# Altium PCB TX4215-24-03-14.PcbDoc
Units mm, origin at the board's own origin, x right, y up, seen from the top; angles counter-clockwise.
Board outline 80.29 x 57.18 mm, 2 copper layers (TopLayer, BottomLayer); 39 components, 49 nets, 94 pads, 680 vias.
Unrouted connection lines stored in the file: 1.
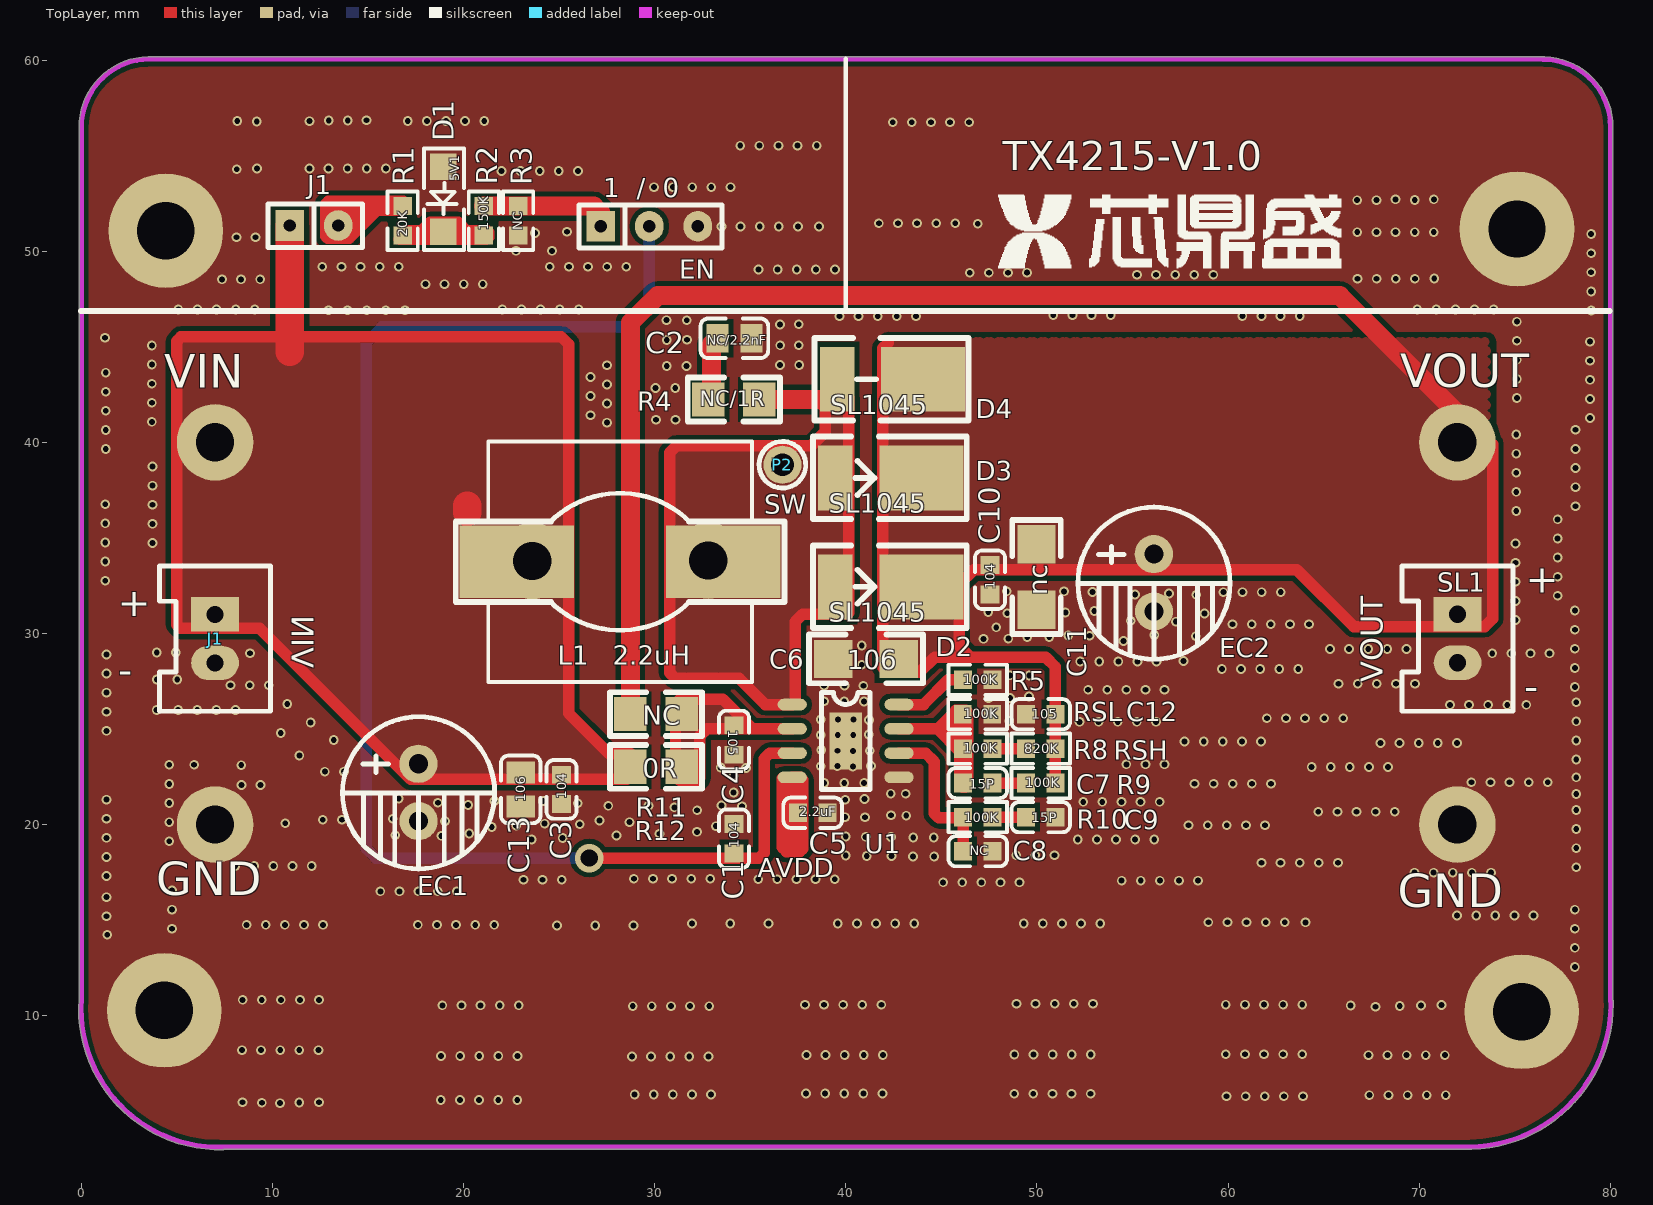
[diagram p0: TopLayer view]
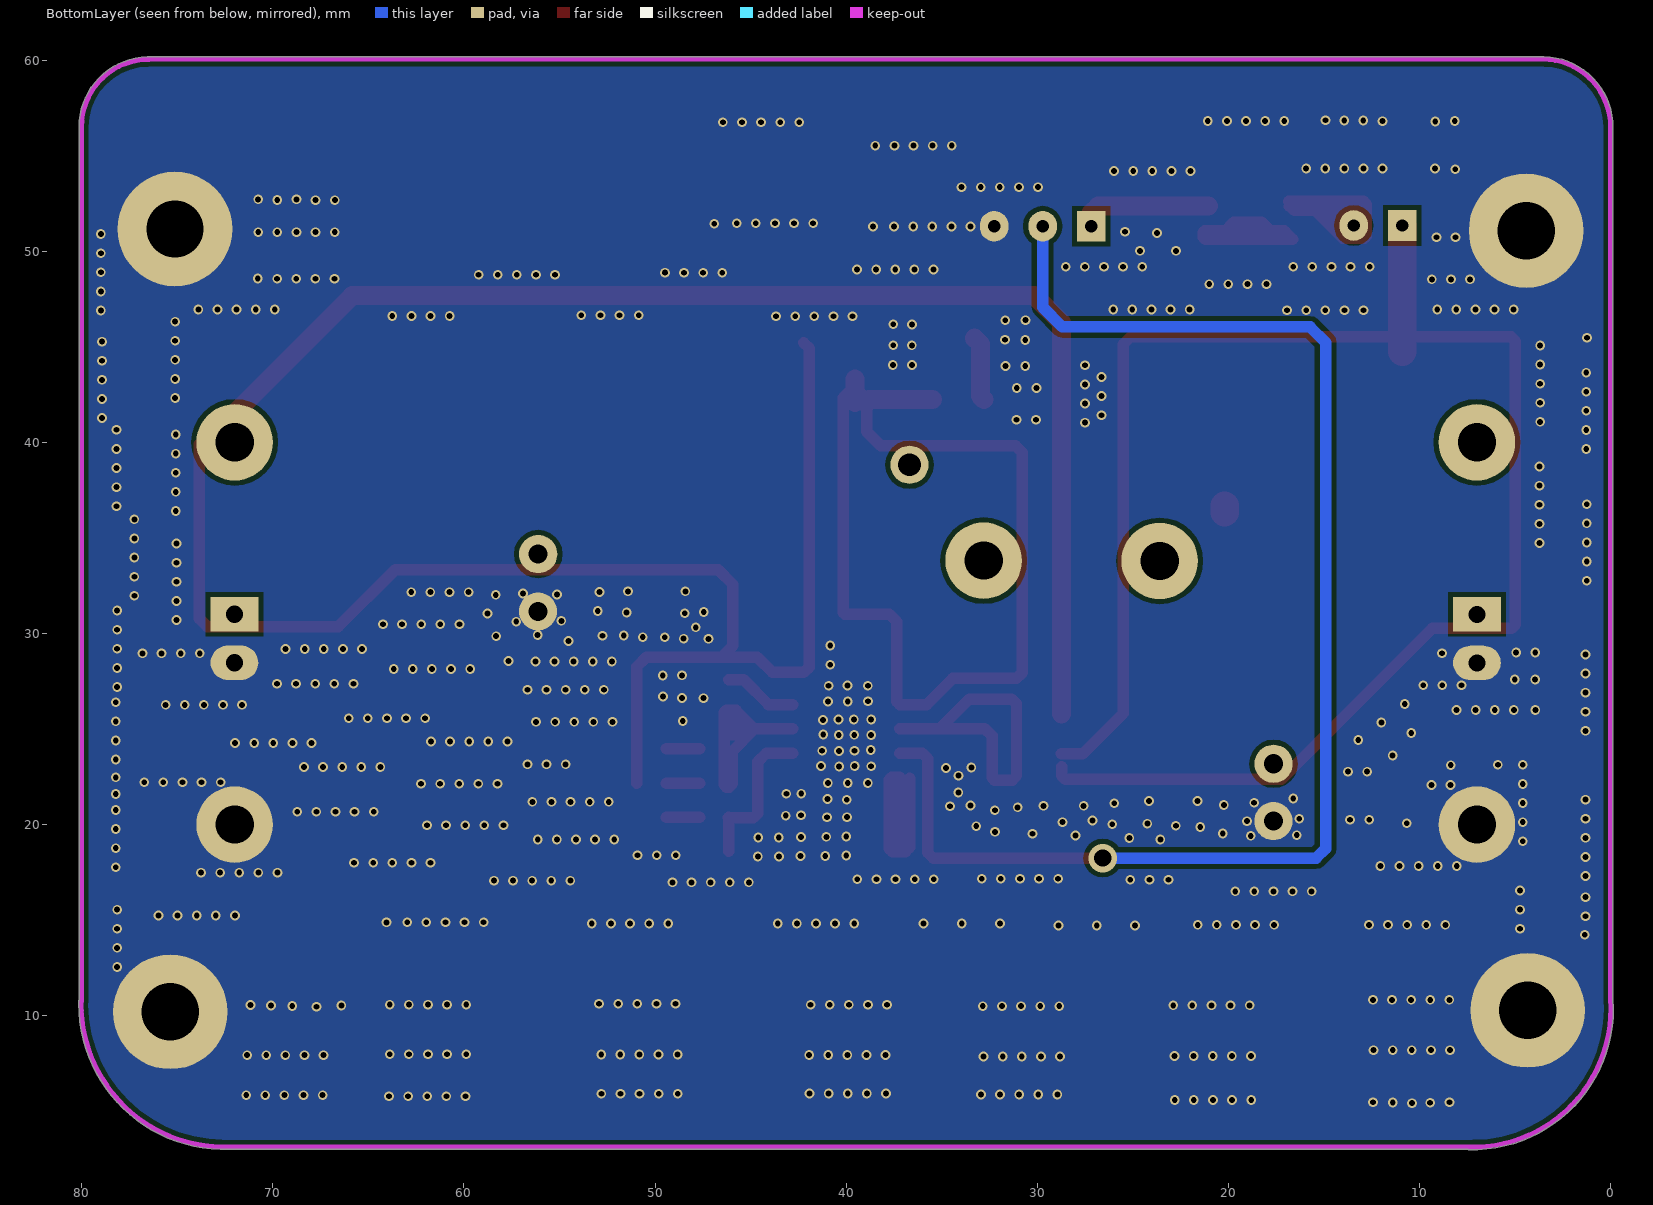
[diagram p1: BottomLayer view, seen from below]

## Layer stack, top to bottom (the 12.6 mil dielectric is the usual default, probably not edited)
TopLayer: signal copper 0.0356
Dielectric: dielectric 0.32, FR-4, Dk 4.8
BottomLayer: signal copper 0.0356

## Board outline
-0.117,10.893 -0.117,56.479 cw(c0.01,56.486) -0.117,56.486 cw(c3.569,56.491) 3.498,60.177 cw(c3.506,60.05) 3.506,60.177 3.514,60.177 cw(c3.569,56.491) 3.563,60.177 cw(c3.564,60.05) 3.574,60.177 76.515,60.177 cw(c76.515,60.05) 76.566,60.166 cw(c76.481,56.511) 80.137,56.511 cw(c76.481,56.511) 80.137,56.509 cw(c80.01,56.5) 80.138,56.5 80.138,10.809 cw(c80.03,10.741) 80.157,10.743 cw(c72.537,10.626) 80.158,10.626 cw(c72.537,10.626) 72.745,3.008 cw(c72.723,3.133) 72.723,3.006 7.467,3.006 cw(c7.417,3.123) 7.421,2.996 cw(c7.238,10.365) -0.116,10.864 cw(c0.011,10.855) -0.116,10.873 cw(c0.01,10.893)

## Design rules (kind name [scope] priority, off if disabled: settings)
Clearance [All] p1: gap=0.254
PolygonConnect [All] p1: connectstyle=Direct reliefconductorwidth=0.254 reliefentries=4 polygonreliefangle="90 Angle"
RoutingVias [All] p1: holewidth=0.3 width=0.4 viastyle="Through Hole" minholewidth=0.3 minwidth=0.4 maxholewidth=0.73 maxwidth=0.4
SilkscreenOverComponentPads SilkToSolderMaskClearance [IsPad] p1: minsilkscreentomaskgap=0.254
SolderMaskExpansion [All] p1: expansion=0.102
TestPointUsage [All] p1: valid=0 allowmultiple=FALSE
Testpoint [All] p1: side=3 testpointundercomponent=TRUE minsize=1.016 maxsize=2.54 preferedsize=1.524 minholesize=0.508 maxholesize=1.016 preferedholesize=0.813 testpointgrid=0.025 style=297 order=0-112345678
Width [All] p1: maxlimit=4.064 minlimit=0.254 preferedwidth=0.6
23 further rules are at their usual default settings.

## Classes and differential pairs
component class ANT8821_EVM_V3: C4 C5 C8 C21 EC1 EC2 J4 J6 J7 J8 J9 L1 L2 L3 L4 L5 LS1 LS2 P1 P2 P4 P5 P6 P9 P10 R1 R10 R12 VBAT
component class ANT8821_EVM_V1: C4 C5 C8 C21 EC1 EC2 J4 J6 J7 J8 J9 L1 L2 L3 L4 L5 LS1 LS2 P1 P2 P4 P5 P6 R1 R10 R12 VBAT
component class NS8258DMEO_V1: C4 C5 C8 C10 C19 C20 EC1 EC2 FB2 J4 J6 J7 J8 J9 J10 J12 L1 LS1 LS2 P1 P4 P5 P6 R1 R10 R12 VBAT
component class NS4158_DEMO: C5 Cb Cc Cg Ci+ Ci- Cp Cv Jin Jp LSo R0/nc Rc1 Rc2 Rf Rg Ri+ Ri- Sc Uic Xi Xig Xo+ Xo- Xv+ Xv-
component class NS4358_2: C4 C5 C8 C10 C19 C20 C21 C22 C28 C29 C30 Cc Cg Ci+ Ci- Cp EC1 EC2 FB2 J8 Jin Jp LS3 P4 R0/nc R1 R10 R19 Rc2 Rf Rg Ro- Uic
component class PA: C4 C5 C8 C10 C19 C20 C21 C22 C28 C53 C62 C66 Cc Ci+ Ci- Cp EC1 EC2 FB2 J8 Jin LS3 R0/nc R1 R10 R19 R46 Rc2 Rf Rg Ro- U3 U8 U9 Uic
component class NS4296_DEMO_V1: C4 C5 C8 C19 C20 EC1 EC2 J4 J7 J8 J9 J10 LS1 LS2 LS3 P1 P4 P5 P6 R1 R10 R12 S3
component class NS4258DMEO_V1: C4 C5 C8 C19 C20 EC1 EC2 J4 J7 J8 J9 J10 LS1 LS2 P1 P4 P5 P6 R1 R10 R12

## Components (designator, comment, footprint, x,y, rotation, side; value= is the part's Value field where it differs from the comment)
C1 "104" LC-0603_C 34.154,19.259 r270 top
C2 "NC/2.2nF" LC-0805_C 34.174,45.445 r0 top
C3 "104" LC-0603_C 25.125,21.842 r270 top
C4 "105" LC-0603_C 34.154,24.424 r90 top
C5 "2.2uF" LC-0603_C 38.268,20.621 r0 top
C6 "106" 1206 42.773,28.669 r180 top
C7 "15P" LC-0603_C 46.907,22.172 r180 top
C8 "NC" LC-0603_C 46.907,18.609 r180 top
C9 "15P" LC-0603_C 50.2,20.39 r180 top
C10 "104" LC-0603_C 47.547,32.813 r270 top
C11 "nc" 1206 49.98,34.675 r270 top
C12 "105" LC-0603_C 50.2,25.776 r180 top
C13 "106" LC-0805_C 22.993,21.842 r270 top
D1 "5V1" DIODER--1N4148_3.4M 18.939,54.424 r270 top
D2 "SL1045" 1812_D 39.66,32.432 r0 top
D3 "SL1045" 1812_D 39.66,38.127 r0 top
D4 "SL1045" 1812_D 39.75,43.292 r0 top
EC1 "" 1000UF/10V 17.638,23.173 r270 top
EC2 "" 1000UF/10V 56.116,34.144 r270 top
EN "1  /  0" SIP-3_2.54 27.167,51.301 r0 top
J1 "VIN" SIP2#1 7,31 r270 top
J1 "" SIP-2_2.54 10.891,51.341 r0 top
L1 "2.2uH" L4 21.291,33.754 r0 top
P2 "TEST_SW" JG1.0 36.687,38.829 r90 top
R1 "20K" LC-0603_R 16.817,51.592 r90 top
R2 "150K" LC-0603_R 21.061,51.592 r90 top
R3 "NC" LC-0603_R 22.863,51.592 r90 top
R4 "NC/1R" 0805 35.285,42.242 r180 top
R5 "100K" LC-0603_R 46.907,27.578 r180 top
R8 "100K" LC-0603_R 46.907,23.974 r180 top
R9 "100K" LC-0603_R 50.2,22.172 r0 top
R10 "100K" LC-0603_R 46.907,20.39 r0 top
R11 "NC" 0805 28.929,25.786 r0 top
R12 "0R" 0805 28.929,23.023 r0 top
RSH "820K" LC-0603_R 50.2,23.974 r0 top
RSL "100K" LC-0603_R 46.897,25.776 r0 top
SL1 "VOUT" SIP2#2 72,31 r270 top
TX4215-V1.0 "Comment" LOGO(18x4)mm 55.706,50.23 r0 top
? "TX4215" ESOP-8 37.197,26.286 r0 top

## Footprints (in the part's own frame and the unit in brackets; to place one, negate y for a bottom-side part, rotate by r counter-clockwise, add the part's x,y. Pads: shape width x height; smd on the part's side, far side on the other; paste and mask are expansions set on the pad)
0805 [mm]
  rect 1.7x1.8 smd: 1(-0.2,0) 2(2.486,0)
  silkscreen extent -1.27,-1.14 3.56,1.14
1000UF/10V [mm]
  round 2 hole 1: 1(-0.009,0.002) 2(2.991,0.012)
  silkscreen extent -2.47,-3.98 5.49,3.99
1206 [mm]
  rect 2x2 smd: 1(0,0) 2(3.429,0)
  silkscreen extent -1.27,-1.27 4.7,1.27
1812_D [mm]
  rect 1.8x3.4 smd: 1(-0.2,0.01)
  rect 4.4x3.4 smd: 2(4.3,0.01)
  silkscreen extent -1.38,-2.14 6.67,2.17
DIODER--1N4148_3.4M [mm]
  rect 1.4x1.4 smd: 1(0,0) 2(3.4,0)
  silkscreen extent -0.95,-1.01 4.36,1.09
ESOP-8 [mil]
  oval 60x24 smd: 1(0.11,-0.16) 2(0.11,-50.16) 3(0.11,-100.16) 4(0.11,-150.16) 5(220.11,-150.16) 6(220.11,-100.16) 7(220.11,-50.16) 8(220.11,-0.16)
  rect 66.93x118.11 smd: 9(110.34,-75.35)
  silkscreen extent 60,-175 160,25
JG1.0 [mm]
  round 2 hole 1.2: 1(0,0)
  silkscreen extent -1.22,-1.22 1.22,1.22
L4 [mm]
  rect 6x3.8 smd: 1(1.5,0) 2(12.3,0)
  silkscreen extent -1.7,-6.3 15.5,6.3
LC-0603_C [mm]
  rect 0.93x0.98 smd: 1(-0.77,0) 2(0.77,0)
  silkscreen extent -1.53,-0.79 1.54,0.79
LC-0603_R [mm]
  rect 0.93x0.98 smd: 1(-0.77,0) 2(0.77,0)
  silkscreen extent -1.53,-0.79 1.54,0.79
LC-0805_C [mm]
  rect 1.16x1.47 smd: 1(-0.89,0) 2(0.89,0)
  silkscreen extent -1.77,-1.03 1.77,1.04
LOGO(18x4)mm [mm]
  silkscreen extent -7.73,-1.09 10.22,2.72
SIP2#1 [mm]
  rect 1.8x2.5 hole 0.9: 1(0,0)
  oval 1.8x2.5 hole 0.9: 2(2.54,0)
  silkscreen extent -2.53,-2.91 5.07,2.9
SIP2#2 [mm]
  rect 1.8x2.5 hole 0.9: 1(-0.006,0.011)
  oval 1.8x2.5 hole 0.9: 2(2.534,0.011)
  silkscreen extent -2.53,-2.9 5.07,2.91
SIP-2_2.54 [mm]
  rect 1.5x1.6 hole 0.65: 1(0.014,0.006)
  oval 1.5x1.6 hole 0.65: 2(2.554,0.006)
  silkscreen extent -1.13,-1.14 3.82,1.12
SIP-3_2.54 [mm]
  rect 1.5x1.6 hole 0.65: 1(0.014,0.006)
  oval 1.5x1.6 hole 0.65: 2(2.554,0.006) 3(5.094,0.006)
  silkscreen extent -1.13,-1.14 6.36,1.12

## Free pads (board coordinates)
  round 6 hole 3: 0(4.344,10.28) 0(4.427,51.077) 0(75.125,51.161) 0(75.365,10.2)
  round 4 hole 2: 0(72,40) 1(23.602,33.794) 1(32.811,33.814) 1(72,20) 2(7,40) 3(7,20)
  round 1.524 on Top Solder: 1(37.247,19.059)

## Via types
v1: diameter 0.508, hole 0.305, TopLayer to BottomLayer, 615 vias
v2: diameter 0.508, hole 0.305, TopLayer to BottomLayer, tented both sides, 64 vias
v3: diameter 1.5, hole 0.9, TopLayer to BottomLayer, 1 vias

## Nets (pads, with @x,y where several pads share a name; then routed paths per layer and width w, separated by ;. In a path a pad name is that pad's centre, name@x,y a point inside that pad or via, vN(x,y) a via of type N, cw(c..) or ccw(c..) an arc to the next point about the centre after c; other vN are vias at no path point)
AGND: 
AVDD: ?.4 C5.1 | length 9
  TopLayer w0.6: ?.4@36.667,22.422 36.667,18.819 36.897,18.589 37.598,18.589 37.748,18.739 37.748,20.621 37.748,22.342 37.618,22.472 ?.4
COMP: ?.6 C8.2 R10.1 | length 8.2
  TopLayer w0.6: ?.6 44.176,23.742 44.635,23.283 44.635,20.581 44.865,20.35 R10.1@46.137,20.35 ; C8.2 R10.1@46.137,20.35 ; R10.1 R10.1@46.137,20.35 ; R10.1@46.177,20.35 R10.1@46.137,20.35
CTRL: 
EN: ?.3 C1.2 EN.1 EN.2 R2.2 R3.2 | length 80.9
  TopLayer w0.6: v3(26.577,18.248) 34.154,18.248 35.455,18.248 35.726,18.518 35.726,23.443 36.025,23.742 ?.3
  TopLayer w1: R2.2 R3.2 26.818,52.362 27.181,51.998 EN.1
  BottomLayer w0.6: v3(26.577,18.248) 15.415,18.248 14.915,18.749 14.915,45.225 15.731,46.041 28.694,46.041 29.721,47.069 EN.2
FB: ?.7 C7.2 R8.2 RSL.1 | length 11.7
  TopLayer w0.6: ?.7 44.787,25.012 44.794,25.005 ; 44.794,25.005 45.765,25.976 46.127,25.976 46.286,25.976 46.307,25.956 46.376,25.886 46.376,25.776 46.376,23.974 46.376,22.172 46.376,22.072 46.307,22.002 46.266,21.962 46.137,21.962 46.126,21.962 46.026,22.062 45.956,22.132 45.956,22.172 45.956,23.844 44.794,25.005
GND: ?.5 ?.9 C1.1 C2.2 C3.2 C4.1 C5.2 C6.2 C8.1 C9.1 C10.2 C11.2 C12.2 C13.2 D1.1 EC1.2 EC2.2 EN.3 J1.2@7,28.46 pad.0@4.344,10.28 pad.0@4.427,51.077 pad.0@75.125,51.161 pad.0@75.365,10.2 pad.1@72,20 pad.3 R3.1 R5.1 RSL.2 SL1.2
  other v1: 10.4,5.425 9.449,5.445 11.401,5.455 8.438,5.475 12.442,5.475 18.813,5.596 19.813,5.596 20.813,5.596 21.813,5.596 22.813,5.596 59.924,5.786 60.924,5.786 61.924,5.786 62.924,5.786 63.924,5.786 67.397,5.846 68.397,5.846 69.397,5.846 70.397,5.846 71.397,5.846 28.953,5.876 29.953,5.876 30.953,5.876 31.953,5.876 32.953,5.876 37.922,5.936 38.922,5.936 39.922,5.936 40.922,5.936 41.922,5.936 48.813,5.916 49.813,5.916 50.813,5.916 51.813,5.916 52.813,5.916 28.813,7.868 29.813,7.868 30.813,7.868 31.813,7.868 32.813,7.868 18.823,7.888 19.823,7.888 20.823,7.888 21.823,7.888 22.823,7.888 67.347,7.938 68.347,7.938 69.347,7.938 70.347,7.938 71.347,7.938 37.942,7.948 38.942,7.948 39.942,7.948 40.942,7.948 41.942,7.948 48.823,7.968 49.823,7.968 50.823,7.968 51.823,7.968 52.823,7.968 59.884,7.988 60.884,7.988 61.884,7.988 62.884,7.988 63.884,7.988 8.408,8.198 9.408,8.198 10.408,8.198 11.408,8.198 12.408,8.198 67.718,10.47 28.853,10.5 29.853,10.5 30.853,10.5 31.853,10.5 32.853,10.5 68.989,10.51 66.416,10.531 70.1,10.531 18.893,10.541 19.893,10.541 20.893,10.541 21.893,10.541 22.893,10.541 71.171,10.561 37.862,10.571 38.862,10.571 39.862,10.571 40.862,10.571 41.862,10.571 59.884,10.581 60.884,10.581 61.884,10.581 62.884,10.581 63.884,10.581 48.933,10.631 49.933,10.631 50.933,10.631 51.933,10.631 52.933,10.631 8.442,10.831 9.442,10.831 10.442,10.831 11.442,10.831 12.442,10.831 78.148,12.552 78.148,13.552 1.361,14.234 4.745,14.553 78.148,14.552 24.889,14.725 26.889,14.725 28.889,14.725 8.653,14.755 9.653,14.755 10.653,14.755 11.653,14.755 12.653,14.755 17.612,14.755 18.612,14.755 19.612,14.755 20.612,14.755 21.612,14.755 31.956,14.825 33.956,14.825 35.956,14.825 39.584,14.825 40.584,14.825 41.584,14.825 42.584,14.825 43.584,14.825 49.313,14.825 50.313,14.825 51.313,14.825 52.313,14.825 53.313,14.825 58.973,14.895 59.973,14.895 60.973,14.895 61.973,14.895 62.973,14.895 64.054,14.885 1.321,15.205 71.986,15.245 72.986,15.245 73.986,15.245 74.986,15.245 75.986,15.245 4.745,15.553 78.148,15.552 1.321,16.206 15.65,16.506 16.65,16.506 4.745,16.553 45.095,16.977 46.095,16.977 47.095,16.977 48.095,16.977 49.095,16.977 54.434,17.067 55.434,17.067 56.434,17.067 57.434,17.067 58.434,17.067 23.136,17.117 24.136,17.117 25.136,17.117 35.419,17.137 36.419,17.137 37.419,17.137 38.419,17.137 39.419,17.137 28.913,17.167 29.913,17.167 30.913,17.167 31.913,17.167 32.913,17.167 1.321,17.307 69.76,17.487 70.76,17.487 71.76,17.487 72.76,17.487 73.76,17.487 78.218,17.768 8.052,17.838 9.052,17.838 10.052,17.838 11.052,17.838 12.052,17.838 61.752,18.008 62.752,18.008 63.752,18.008 64.752,18.008 65.752,18.008 1.321,18.307 43.523,18.328 44.625,18.328 42.392,18.358 40,18.378 50.919,18.398 78.218,18.768 4.605,19.129 52.142,19.219 53.142,19.219 54.142,19.219 55.142,19.219 56.142,19.219 1.321,19.307 43.533,19.329 44.605,19.329 40,19.379 18.839,19.409 16.426,19.449 28.008,19.429 20.3,19.53 32.212,19.62 78.218,19.768 21.481,19.87 33.193,19.92 57.938,19.97 58.938,19.97 59.938,19.97 60.938,19.97 61.938,19.97 26.086,20.02 10.671,20.07 4.605,20.129 28.689,20.13 19.029,20.18 27.117,20.22 12.637,20.25 13.637,20.25 1.321,20.307 16.296,20.31 39.96,20.39 41.011,20.38 42.362,20.49 43.163,20.47 64.725,20.671 65.725,20.671 66.725,20.671 67.725,20.671 68.725,20.671 32.222,20.751 78.218,20.768 27.578,20.981 20.24,21.021 25.976,21.121 4.605,21.129 18.659,21.141 52.422,21.191 53.422,21.191 54.422,21.191 55.422,21.191 56.422,21.191 21.622,21.231 24.154,21.231 39.97,21.301 1.321,21.307 40.981,21.341 16.607,21.361 78.218,21.602 42.352,21.622 43.133,21.612 8.38,22.072 9.38,22.072 4.605,22.129 58.248,22.142 59.248,22.142 60.248,22.142 61.248,22.142 62.248,22.142 38.869,22.182 39.92,22.182 40.961,22.182 72.733,22.212 73.733,22.212 74.733,22.212 75.733,22.212 76.733,22.212 78.218,22.472 12.747,22.773 13.747,22.773 34.785,22.963 33.453,22.993 64.374,23.013 65.374,23.013 66.374,23.013 67.374,23.013 68.374,23.013 40.37,23.043 39.561,23.062 4.605,23.129 5.906,23.133 8.368,23.113 78.218,23.402 11.411,23.614 39.57,23.864 40.38,23.854 67.978,24.274 68.978,24.274 69.978,24.274 70.978,24.274 71.978,24.274 57.728,24.344 58.728,24.344 59.728,24.344 60.728,24.344 61.728,24.344 78.218,24.402 13.213,24.424 39.58,24.695 40.39,24.685 10.434,24.795 1.321,24.905 12.002,25.345 52.232,25.375 53.232,25.375 54.232,25.375 55.232,25.375 56.232,25.375 78.218,25.402 48.559,25.425 39.6,25.495 40.4,25.495 62.032,25.566 63.032,25.566 64.032,25.566 65.032,25.566 66.032,25.566 1.321,25.905 3.944,25.996 5.068,25.996 6.068,25.996 7.068,25.996 8.068,25.996 71.612,26.266 72.612,26.266 73.612,26.266 74.612,26.266 75.612,26.266 10.781,26.306 78.218,26.402 39.92,26.436 40.951,26.436 38.859,26.455 47.467,26.617 48.589,26.627 49.59,26.707 1.321,26.905 52.683,27.057 53.683,27.057 54.683,27.057 55.683,27.057 56.683,27.057 78.148,27.197 38.869,27.267 40.921,27.267 7.812,27.287 8.812,27.287 9.812,27.287 65.786,27.367 66.786,27.367 67.786,27.367 68.786,27.367 69.786,27.367 3.954,27.598 5.025,27.598 1.321,27.905 59.68,28.138 60.68,28.138 61.68,28.138 62.68,28.138 63.68,28.138 78.148,28.197 40.841,28.367 53.262,28.539 54.262,28.539 55.262,28.539 56.262,28.539 57.668,28.559 1.321,28.905 8.829,28.969 73.824,28.959 74.824,28.959 75.824,28.959 76.824,28.959 3.948,29.009 4.948,29.009 65.335,29.189 66.335,29.189 69.335,29.189 78.148,29.197 40.841,29.367 54.534,29.61 47.207,29.72 48.508,29.73 49.499,29.8 50.651,29.81 58.318,29.86 56.146,29.92 78.148,30.197 47.878,30.32 60.24,30.48 61.24,30.48 62.24,30.48 63.24,30.48 64.24,30.48 57.267,30.621 54.905,30.661 75.045,30.705 58.769,31.041 48.448,31.061 51.491,31.101 47.457,31.121 53.003,31.171 78.148,31.197 75.045,31.705 77.247,31.972 58.338,32.022 55.135,32.042 56.917,32.092 52.913,32.172 59.759,32.162 60.759,32.162 61.759,32.162 62.759,32.162 48.418,32.202 51.421,32.202 75.045,32.705 1.251,32.763 77.247,32.972 75.045,33.705 1.251,33.763 77.247,33.972 75.045,34.705 3.724,34.735 1.251,34.763 77.247,34.972 3.724,35.735 1.251,35.763 77.247,35.972 75.085,36.41 78.178,36.657 3.724,36.735 1.251,36.763 75.085,37.41 78.178,37.657 3.724,37.735 75.085,38.41 78.178,38.657 3.724,38.735 75.085,39.41 1.281,39.65 78.178,39.657 75.085,40.41 1.281,40.65 78.178,40.657 27.507,41.031 3.694,41.071 30.07,41.181 31.091,41.181 78.939,41.271 26.647,41.421 1.281,41.65 27.507,42.031 3.694,42.071 78.939,42.271 75.115,42.316 26.647,42.421 1.281,42.65 30.05,42.843 31.081,42.843 27.507,43.031 3.694,43.071 78.939,43.271 26.647,43.421 1.281,43.65 30.631,43.994 27.507,44.031 3.694,44.071 78.939,44.271 3.694,45.071 78.939,45.271 75.115,45.316 1.241,45.475 75.115,46.316 30.621,46.396 60.751,46.607 61.751,46.607 62.751,46.607 63.751,46.607 50.861,46.647 51.861,46.647 52.861,46.647 53.861,46.647 78.999,46.897 12.933,46.917 13.933,46.917 14.933,46.917 15.933,46.917 16.933,46.917 5.079,46.947 6.079,46.947 7.079,46.947 8.079,46.947 9.079,46.947 22.032,46.947 23.032,46.947 24.032,46.947 25.032,46.947 26.032,46.947 69.9,46.947 70.9,46.947 71.9,46.947 72.9,46.947 73.9,46.947 78.999,47.897 18.008,48.278 19.008,48.278 20.008,48.278 21.008,48.278 7.359,48.528 8.359,48.528 9.359,48.528 66.776,48.559 67.776,48.559 68.776,48.559 69.776,48.559 70.791,48.569 55.235,48.769 56.235,48.769 57.235,48.769 58.235,48.769 59.235,48.769 46.486,48.879 47.486,48.879 48.486,48.879 49.48,48.88 49.486,48.879 78.999,48.897 35.435,49.049 36.435,49.049 37.435,49.049 38.435,49.049 39.435,49.049 12.613,49.189 13.613,49.189 14.613,49.189 15.613,49.189 16.613,49.189 24.514,49.189 25.514,49.189 26.514,49.189 27.514,49.189 28.514,49.189 78.999,49.897 22.743,50.02 24.635,50.02 8.119,50.731 9.119,50.731 78.999,50.897 23.744,50.951 25.415,51.021 66.767,51.001 67.767,51.001 68.767,51.001 69.767,51.001 70.767,51.001 33.497,51.291 36.497,51.291 37.497,51.291 38.599,51.291 46.907,51.441 41.732,51.461 42.732,51.461 43.732,51.461 44.732,51.461 45.732,51.461 66.757,52.673 67.768,52.673 69.77,52.683 68.769,52.713 70.771,52.713 21.986,54.194 23.986,54.194 24.986,54.194 25.986,54.194 8.138,54.294 9.189,54.334 11.936,54.334 12.936,54.334 13.936,54.334 14.936,54.334 15.936,54.334 34.478,55.525 35.478,55.525 36.478,55.525 37.478,55.525 38.478,55.525 42.456,56.747 43.456,56.747 44.456,56.747 45.456,56.747 46.456,56.747 9.179,56.787 11.942,56.807 8.158,56.817 12.953,56.837 13.944,56.837 17.081,56.817 18.081,56.817 20.081,56.817 21.081,56.817 14.925,56.857
  other v2: 17.65,16.506 18.65,16.506 19.65,16.506 41.101,18.358 48.919,18.398 49.919,18.398 23.564,19.219 25.185,19.299 42.372,19.349 41.041,19.359 30.25,19.52 22.753,19.94 24.244,20.05 31.031,20.901 34.575,20.961 29.683,20.981 33.503,21.001 34.134,21.682 34.124,22.563 38.699,23.052 41.321,23.062 54.683,23.153 55.683,23.153 56.683,23.153 41.261,23.863 38.719,23.903 38.699,24.684 41.201,24.714 38.699,25.494 41.221,25.474 39.93,27.276 48.589,27.808 49.6,27.798 52.262,28.539 67.335,29.189 68.335,29.189 52.753,29.88 51.642,29.9 75.115,43.316 31.662,43.994 36.56,44.044 37.56,44.044 75.115,44.316 36.567,45.075 37.537,45.085 30.631,45.355 31.692,45.365 36.557,46.166 37.537,46.176 31.682,46.386 39.67,46.597 40.67,46.597 41.67,46.597 42.67,46.597 43.67,46.597 34.497,51.291 35.497,51.291 29.964,53.353 30.964,53.353 31.964,53.353 32.964,53.353 33.964,53.353 22.986,54.194 19.081,56.817
INL: 
INN: 
INP: 
INR: 
NetC10_1: 
NetLED1_1: 
NetLED1_2: 
NetLED2_1: 
NetLED2_2: 
NetLED3_1: 
NetLED3_2: 
NetLED4_1: 
NetLED4_2: 
NetR1_1: 
NetR1_2: 
NetR2_1: D1.2 R1.1 R2.1 | length 10
  TopLayer w0.6: R1.1@16.647,50.631 21.221,50.631 21.331,50.741 21.331,51.001 21.251,51.081 20.15,51.081 19.72,51.511 18.258,51.511 17.818,51.071 17.077,51.071 16.828,50.822 R1.1
NetR2_2: 
NetR3_2: 
NetR4_2: C2.1 R4.2 | length 3.4
  TopLayer w1: R4.2 32.983,42.426 32.983,45.144 C2.1
NetR5_1: 
NetR6_2: 
NetR9_1: C7.1 R9.1 | length 1.8
  TopLayer w0.6: C7.1 R9.1
NetR9_2: 
NetR10_2: R8.1 RSH.1 | length 1.8
  TopLayer w0.6: R8.1 RSH.1
NetR11_2: 
NetR17_1: C9.2 R10.2 | length 1.8
  TopLayer w0.6: R10.2 C9.2
NetS1_5: 
NetS1_6: 
NetS1_7: 
NetS1_8: 
OC: ?.8 R5.2 | length 3.9
  TopLayer w0.6: ?.8 44.07,26.282 45.365,27.578 R5.2
PVDD: C6.1 C10.1 C11.1 C12.1 D2.2 D3.2 D4.2 EC2.1 pad.0@72,40 R9.2 R11.1 RSH.2 SL1.1 | length 144.2
  TopLayer w0.6: 42.222,45.205 42.184,45.167 41.942,44.925 41.942,43.302 41.942,38.137 41.942,32.443 41.942,28.669 41.942,28.238 42.142,28.038 42.212,27.968 42.773,27.968 43.864,27.968 44.655,28.759 46.526,28.759 ; R9.2 RSH.2 C12.1 50.97,28.249 50.46,28.759 46.526,28.759 ; pad.0@73.844,39.91 73.844,30.771 73.433,30.36 72.011,30.36 66.577,30.36 63.604,33.333 56.118,33.333 47.547,33.333 46.697,33.333 45.926,32.563 45.926,32.443 45.926,29.359 46.526,28.759
  TopLayer w1: R11.1 28.729,46.261 30.146,47.678 65.847,47.678 72,41.524 72,40 pad.0@72.09,39.91
PVIN: C3.1 C13.1 EC1.1 J1.1 L1.1 pad.1@23.602,33.794 pad.2 R12.1 | length 93.3
  TopLayer w0.6: R12.1 28.729,22.563 28.539,22.372 25.125,22.372 22.993,22.372 17.639,22.372 17.227,22.372 17.028,22.571 9.329,30.27 7,30.27 5.185,30.27 4.995,30.46 4.995,40 4.995,45.295 5.215,45.515 10.905,45.515 25.125,45.515 25.495,45.145 25.495,33.794 25.495,33.754 25.495,25.826 27.618,23.704 28.729,23.704 R12.1@28.739,23.704
  TopLayer w1.5: 10.905,44.742 10.905,45.515 J1.1@10.905,51.348
SPK+: 
SPK-: 
SW: ?.1 D2.1 D3.1 D4.1 L1.2 P2.1 pad.1@32.811,33.814 R4.1 | length 55.2
  TopLayer w0.6: D4.1@38.829,42.002 38.649,42.182 38.829,42.182 D4.1@38.859,42.182 ; D4.1@38.939,42.072 D4.1@38.849,41.982 ; D4.1@39.459,42.182 D4.1@38.859,42.182 ; D4.1@38.849,41.982 38.929,41.902 38.929,40.561 38.188,39.82 36.687,39.82 31.141,39.82 30.791,39.469 30.791,33.814 30.791,33.754 30.791,27.948 31.091,27.648 34.424,27.648 35.79,26.282 ?.1 37.357,26.44 37.357,30.621 37.738,31.001 39.459,31.001 40.07,31.001 40.16,31.091 40.16,32.443 40.16,38.137 40.16,42.342 39.88,42.623 39.549,42.623 39.299,42.623 D4.1@38.859,42.182 ; D4.1@38.849,41.982 38.849,42.162 38.849,42.172 D4.1@38.859,42.182
  TopLayer w1: R4.1 38.829,42.242 38.829,42.182 38.849,42.162 D4.1@38.939,42.072 ; D4.1@39.459,42.182 39.549,42.092 39.549,42.623 D4.1
VBAT: 
VCC: J1.2@13.445,51.348 R1.2 | length 10.5
  TopLayer w0.6: R1.2 16.796,52.362 16.567,52.132 15.465,52.132 14.014,50.681 12.903,50.681 12.793,50.791 12.793,52.472 12.933,52.613 R1.2@16.837,52.613
VIN: ?.2 C4.2 R11.2 R12.2 | length 17.1
  TopLayer w0.6: ?.2 35.118,25.012 ; 35.118,25.012 34.545,25.585 33.564,26.567 31.415,26.567 31.331,26.567 31.091,26.326 31.091,25.786 31.091,23.023 31.091,22.543 31.301,22.332 31.415,22.332 32.262,22.332 32.372,22.442 32.372,23.023 32.372,24.645 32.464,24.736 32.624,24.897 32.74,25.012 34.154,25.012 35.118,25.012
VON: 
VOP: 
VOUT: 
copper on no net: | length 0.3
  TopLayer w1.5: 20.19,36.346 20.19,36.687

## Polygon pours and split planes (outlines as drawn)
PVIN on TopLayer "TopLayer-PVIN" (hatched 45Degree grid 0.4 track 0.5, remove dead copper, pour order 4): 5.265,45.315 5.265,30.47 9.55,30.47 17.457,22.563 29.199,22.563 29.199,23.463 27.708,23.463 25.195,25.976 25.195,45.225 5.255,45.225
PVDD on TopLayer "TopLayer-PVDD" (hatched 45Degree grid 0.4 track 0.5, remove dead copper, pour order 3): 42.232,45.265 42.232,28.078 43.513,28.078 44.264,28.829 45.636,28.829 45.636,32.613 46.597,33.574 63.814,33.574 66.657,30.731 73.513,30.731 73.513,45.255 42.242,45.255
SW on TopLayer "TopLayer-SW" (hatched 45Degree grid 0.4 track 0.5, remove dead copper, pour order 2): 31.101,39.469 31.101,28.038 34.314,28.038 35.866,26.486 37.077,26.486 37.077,30.691 37.598,31.211 39.84,31.211 39.84,42.492 39.139,42.492 39.139,40.611 38.068,39.539 31.171,39.539
VIN on TopLayer "TopLayer-VIN" (hatched 45Degree grid 0.4 track 0.5, remove dead copper, pour order 1): 31.141,26.456 31.141,22.422 32.162,22.422 32.162,25.045 34.715,25.045 33.503,26.256 31.301,26.256
GND on TopLayer "TopLayer-No Net" (solid, remove dead copper, pour order 1000): -1.351,61.441 82.142,61.441 82.232,61.531 82.312,61.451 82.312,3.163 -1.091,3.163 -1.261,2.993
GND on BottomLayer "TopLayer-No Net" (solid, remove dead copper, pour order 1001): -1.732,61.291 81.762,61.291 81.852,61.381 81.932,61.301 81.932,3.013 -1.471,3.013 -1.642,2.843

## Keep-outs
KeepOutLayer:
  lines w0.254: 0.011,10.855 ccw(c7.238,10.365) 7.417,3.123 ; 0.01,10.893 0.01,56.5 ; 0.01,56.486 cw(c3.569,56.491) 3.564,60.05 ; 3.506,60.05 76.515,60.05 ; 7.437,3.123 7.447,3.133 72.723,3.133 ; 72.653,3.133 ccw(c72.537,10.626) 80.03,10.741 ; 76.486,60.04 cw(c76.481,56.511) 80.01,56.506 ; 80.01,10.735 80.01,56.5

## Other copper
TopLayer:
  rectangle net NetR2_1: 17.968,50.581 20.01,51.431
  rectangle net VCC: 12.793,50.47 13.984,51.091
  rectangle net VCC: 12.643,50.901 14.595,51.902
  rectangle net VCC: 12.843,51.632 15.295,52.492
  rectangle net AVDD: 36.627,18.569 37.808,22.462
  rectangle net FB: 45.135,24.394 46.516,25.475
  rectangle net FB: 45.475,25.055 46.406,25.796

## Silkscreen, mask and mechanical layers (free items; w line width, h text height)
TopOverlay:
  lines w0.254: 40,46.897 40,60.05
  lines w0.3: -0.02,46.871 79.98,46.871
  lines w0.305: 40.609,31.552 41.5,32.443 40.609,33.334 ; 40.609,37.246 41.5,38.137 40.609,39.028
  text "VOUT" at 69.009,42.312 h3
  text "VIN" at 4.354,42.292 h3
  text "SW" at 35.746,36.256 h1
  text "+" at 75.576,32.132 h1.5
  text "+" at 1.902,30.911 h1.5
  text "-" at 1.942,27.367 h1.5
  text "-" at 75.495,26.516 h1.5
  text "U1" at 41.001,18.488 h1
  text "AVDD" at 35.395,17.247 h1
  text "GND" at 3.924,15.716 h3
  text "GND" at 68.869,15.095 h3
TopSolder:
  rectangle: 41.642,34.755 46.236,35.836
  rectangle: 38.448,34.755 40.46,35.836
  lines w1.5: 8.188,35.445 12.703,35.445 19.189,28.959 22.853,28.959 ; 9.049,32.332 11.522,32.332 17.818,26.036 23.714,26.036 ; 9.74,38.258 14.254,38.258 17.823,34.69 ; 10.631,41.041 15.556,41.041 18.999,37.598 ; 48.388,43.193 66.987,43.193 69.229,40.951 ; 48.458,39.96 65.746,39.96 70.891,34.815 ; 48.538,36.837 64.675,36.837 69.209,32.302
BottomSolder:
  rectangle: 51.652,27.998 54.084,30.51
  rectangle: 58.128,27.908 60.56,30.42
  rectangle: 62.332,27.938 64.765,30.45
  rectangle: 66.667,27.938 69.099,30.45
  rectangle: 66.667,23.624 69.099,26.136
  rectangle: 62.332,23.624 64.765,26.136
  rectangle: 58.168,23.483 60.601,25.996
  rectangle: 51.662,23.584 54.094,26.096
  rectangle: 66.667,18.849 69.099,21.361
  rectangle: 62.342,18.859 64.775,21.371
  rectangle: 58.198,18.729 60.631,21.241
  rectangle: 51.832,18.609 54.264,21.121
  rectangle: 45.966,27.908 48.398,30.42
  rectangle: 41.802,27.788 44.234,30.3
  rectangle: 37.137,27.758 39.57,30.27
  rectangle: 31.712,27.678 34.144,30.19
  rectangle: 26.867,27.638 29.299,30.15
  rectangle: 22.252,27.728 24.685,30.24
  rectangle: 18.038,27.698 20.47,30.21
  rectangle: 10.531,22.563 12.963,25.075
  rectangle: 10.5,27.668 12.933,30.18
  rectangle: 46.056,23.564 48.488,26.076
  rectangle: 41.892,23.564 44.324,26.076
  rectangle: 37.147,23.594 39.58,26.106
  rectangle: 31.732,23.564 34.164,26.076
  rectangle: 26.877,23.564 29.309,26.076
  rectangle: 22.242,23.564 24.675,26.076
  rectangle: 46.026,18.639 48.458,21.151
  rectangle: 41.922,18.609 44.354,21.121
  rectangle: 37.197,18.579 39.63,21.091
  rectangle: 31.662,18.639 34.094,21.151
  rectangle: 10.5,18.609 12.933,21.121
  rectangle: 10.531,13.233 12.963,15.746
  rectangle: 18.008,13.233 20.44,15.746
  rectangle: 22.302,13.233 24.735,15.746
  rectangle: 26.787,13.263 29.219,15.776
  rectangle: 31.632,13.233 34.064,15.746
  rectangle: 37.127,13.233 39.56,15.746
  rectangle: 41.892,13.203 44.324,15.716
  rectangle: 45.936,13.203 48.368,15.716
  rectangle: 51.682,13.263 54.114,15.776
  rectangle: 58.168,13.233 60.601,15.746
  rectangle: 62.312,13.263 64.745,15.776
  rectangle: 66.536,13.263 68.969,15.776

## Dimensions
0.01,56.5 to 80.01,56.5 on TopOverlay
